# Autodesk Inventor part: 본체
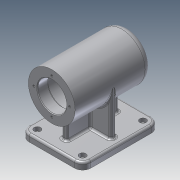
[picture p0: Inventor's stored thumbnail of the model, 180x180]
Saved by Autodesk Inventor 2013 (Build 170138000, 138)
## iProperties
Created: 2020-10
Part Number: 본체
Material: 알루미늄 6061
Document SubType Name: Modeling
Designer: CADCOM
Density: 2.71 g/cm^3
Mass: 1034.1 g
Surface Area: 760.39 cm^2
Volume: 381.585 cm^3
Author: CADCOM
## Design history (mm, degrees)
sketch "스케치1"
  geometry: C1 r 34 at (0, 0); 1 further point
  constraints: 1 centre point, 1 coincident
  dimensions: "d0" = 68 diameter of C1
extrude "돌출1" new body sketch "스케치1" distance "d1" = 112; taper "d2" = 0 deg
sketch "스케치2"
  geometry: L1 (-112, 34)-(0, 34) reference; L2 (0, 34)-(0, -34) reference; L3 (0, -34)-(-112, -34) reference; L4 (-112, -34)-(-112, 34) reference; L5 (-112, 0)-(0, 0); L6 (0, 0)-(0, 21); L7 (0, 21)-(-15, 21); L8 (-15, 21)-(-15, 24); L9 (-15, 24)-(-69, 24); L10 (-69, 24)-(-69, 21); L11 (-69, 21)-(-81, 21); L12 (-81, 21)-(-81, 17.5); L13 (-81, 17.5)-(-99, 17.5); L14 (-99, 17.5)-(-99, 16); L15 (-99, 16)-(-103, 16); L16 (-103, 16)-(-103, 10.5); L17 (-103, 10.5)-(-106, 10.5); L18 (-106, 10.5)-(-106, 0)
  constraints: 28 end point, 6 parallel, 6 perpendicular, 2 point on line, 1 collinear, 1 midpoint
  dimensions: "d3" = 15 distance of L6.end L7.end; "d5" = 54 distance of L8.end L9.end; "d6" = 12 distance of L10.end L11.end; "d7" = 18 distance of L12.end L13.end; "d8" = 4 distance of L14.end L15.end; "d9" = 3 distance of L16.end L17.end; "d10" = 42 diameter of L7 L5; "d11" = 48 diameter of L9 L5; "d12" = 42 diameter of L11 L5; "d13" = 35 diameter of L13 L5; "d14" = 32 diameter of L15 L5; "d15" = 21 diameter of L17 L5
revolve "회전1" sketch "스케치2" stored, may be unused: angle "d16" = 90 deg
node "작업 평면1"
sketch "스케치3"
  geometry: L1 (112, -34)-(112, 34) reference; L2 (0, 34)-(0, -34) reference; L3 (0, 34)-(112, 34) reference; L4 (0, -34)-(112, -34) reference; L5 (0, 0)-(112, 0); L6 (56, 34)-(56, -34); L7 (0, -45)-(112, -45); L8 (112, -45)-(112, 45); L9 (112, 45)-(0, 45); L10 (0, 45)-(0, -45); L11 (0, -45)-(112, 45); L12 (112, -45)-(0, 45); 1 further point
  constraints: 16 end point, 6 midpoint, 2 parallel, 1 horizontal, 1 perpendicular
  dimensions: "d18" = 112 distance of L8.end L9.end; "d20" = 90 distance of L7.end L8.end
extrude "돌출2" join sketch "스케치3" distance "d21" = 10; taper "d22" = 0 deg
sketch "스케치4"
  geometry: L1 (0, -45)-(112, -45) reference; L2 (112, -45)-(112, 45) reference; L3 (112, 45)-(0, 45) reference; L4 (0, 45)-(0, -45) reference; L5 (0, 0)-(112, 0); L6 (18, 4)-(94, 4); L7 (94, 4)-(94, -4); L8 (94, -4)-(18, -4); L9 (18, -4)-(18, 4); L10 (56, 45)-(56, -45); 1 further point
  constraints: 12 end point, 4 midpoint, 2 parallel, 1 horizontal, 1 horizontal alignment, 1 perpendicular
  dimensions: "d24" = 8 distance of L6.end L7.end; "d26" = 18 distance between parallel lines of L2 L7; "d27" = 18 distance between parallel lines of L4 L9
extrude "돌출3" join sketch "스케치4" stored distance "d28" = 10; taper "d29" = 0 deg
node "작업 평면2"
sketch "스케치5"
  geometry: L1 (-45, -74)-(-45, -64) reference; L2 (-45, -64)-(-4, -64) reference; L3 (-4, -64)-(-4, -33.764) reference; L4 (4, -33.764)-(4, -64) reference; L5 (4, -64)-(45, -64) reference; L6 (45, -64)-(45, -74) reference; L7 (45, -74)-(-45, -74) reference; L8 (-34, 0)-(-34, -64); L9 (34, 0)-(34, -64); C1 r 24 at (0, 0) reference; A1 r 34 centre (0, 0) between (4, -33.764) and (-4, -33.764) reference; 1 further point
  constraints: 4 end point, 2 perpendicular, 2 point on circle, 2 point on line
  dimensions: "d31" = 68 distance between parallel lines of L9 L8; "d32" = 11 distance between parallel lines of L8 L1
feature "리브1" sketch "스케치5" dims "d33" = 1, "d34" = 8, "d35" = 0, "d36" = 0, "d37" = 1, "d38" = 1
fillet "모깎기1" dims "d50" = 12
sketch "스케치7"
  geometry: C1 r 4.75 at (12, 33); C2 r 4.75 at (100, 33); C3 r 4.75 at (100, -33); C4 r 4.75 at (12, -33); A1 r 12 centre (12, 33) between (12, 45) and (0, 33) reference; A2 r 12 centre (12, -33) between (0, -33) and (12, -45) reference; A3 r 12 centre (100, -33) between (100, -45) and (112, -33) reference; A4 r 12 centre (100, 33) between (112, 33) and (100, 45) reference; 1 further point
  constraints: 4 centre point, 4 coincident
  dimensions: "d51" = 9.5 diameter of C1; "d52" = 9.5 diameter of C2; "d53" = 9.5 diameter of C3; "d54" = 9.5 diameter of C4
extrude "돌출4" cut sketch "스케치7" distance "d55" = 5.4; taper "d56" = 0 deg
sketch "스케치8"
  geometry: C1 r 2.75 at (12, 33); C2 r 2.75 at (100, 33); C3 r 2.75 at (100, -33); C4 r 2.75 at (12, -33); A1 r 12 centre (12, 33) between (12, 45) and (0, 33) reference; A2 r 12 centre (12, -33) between (0, -33) and (12, -45) reference; A3 r 12 centre (100, -33) between (100, -45) and (112, -33) reference; A4 r 12 centre (100, 33) between (112, 33) and (100, 45) reference; 1 further point
  constraints: 4 centre point, 4 coincident
  dimensions: "d57" = 5.5 diameter of C1; "d58" = 5.5 diameter of C2; "d59" = 5.5 diameter of C3; "d60" = 5.5 diameter of C4
extrude "돌출5" cut sketch "스케치8" stored distance "d61" = 5.4; taper "d62" = 0 deg
sketch "스케치9"
  geometry: L1 (88, 0)-(0, 0) reference; L2 (100, -10)-(100, 0) reference; L3 (-12, 0)-(-12, -10) reference; 2 further points
  constraints: 1 other
  dimensions: "d64" = 3 distance from line of L1 point (44, -3); "d77" = 56 distance from line of L3 point (44, -3)
feature "엠보싱1" sketch "스케치9" dims "d65" = 0.5, "d66" = 0
fillet "모깎기2" dims "d67" = 3
fillet "모깎기3" dims "d68" = 3
fillet "모깎기4" dims "d69" = 3
fillet "모깎기5" dims "d70" = 10
fillet "모깎기6" dims "d71" = 3
fillet "모깎기7" dims "d72" = 3
chamfer "모따기1" distance "d73" = 1; stored, may be unused: second distance "d74" = 2, angle "d75" = 45 deg
fillet "모깎기8" dims "d76" = 0.3
sketch "스케치10" dims "d79" = 52
  geometry: C1 r 34 at (0, 0) reference; C2 r 22 at (0, 0) reference; 2 further points
  constraints: 2 horizontal alignment, 1 coincident, 2 other
hole "구멍2" sketch "스케치10" at (26, 0) diameter "d80" = 3.242; stored, may be unused: countersink angle "d84" = 90 deg, drill point angle "d86" = 118 deg; dims "d81" = 8, "d82" = 4, "d83" = 2, "d85" = 11
node "솔리드1"
mirror "대칭1"
pattern_circular "원형 패턴2" dims angle "d88" = 360 deg
node "투영된 루프1"
node "절단 모서리 투영1"
node "절단 모서리 투영2"
other parameters: "d17" = -74, "d30" = 56
